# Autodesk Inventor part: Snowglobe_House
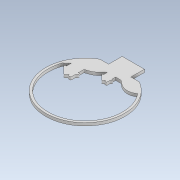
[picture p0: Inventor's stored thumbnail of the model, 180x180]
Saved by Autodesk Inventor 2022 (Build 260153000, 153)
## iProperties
Created: 2021-12
Part Number: Snowglobe_House
Material: Generic
Document SubType Name: Modeling
Designer: allis
Density: 1 g/cm^3
Appearance: Default
Author: allis
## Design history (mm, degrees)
sketch "Sketch1"
  geometry: L1 (18.282, -77.899)-(18.439, -77.803); L2 (18.439, -77.803)-(18.526, -77.758); L3 (18.526, -77.758)-(18.604, -77.703); L4 (18.604, -77.703)-(22.58, -74.861); L5 (22.58, -74.861)-(26.905, -74.228); L6 (26.905, -74.228)-(31.532, -75.726); L7 (31.532, -75.726)-(34.469, -76.677); L8 (34.469, -76.677)-(36.957, -78.398); L9 (36.957, -78.398)-(39.204, -80.475); L10 (39.204, -80.475)-(39.975, -81.188); L11 (39.975, -81.188)-(40.866, -81.529); L12 (40.866, -81.529)-(41.886, -81.542); L13 (41.886, -81.542)-(43.502, -81.564); L14 (43.502, -81.564)-(45.119, -81.548); L15 (45.119, -81.548)-(46.737, -81.548); L16 (46.737, -81.548)-(46.737, -80.096); L17 (46.737, -80.096)-(46.737, -78.696); L18 (46.737, -78.696)-(46.737, -77.291); L19 (46.737, -77.291)-(46.639, -77.297); L20 (46.639, -77.297)-(46.582, -77.296); L21 (46.582, -77.296)-(46.526, -77.303); L22 (46.526, -77.303)-(46.142, -77.355); L23 (46.142, -77.355)-(45.826, -77.267); L24 (45.826, -77.267)-(45.645, -76.887); L25 (45.645, -76.887)-(45.465, -76.51); L26 (45.465, -76.51)-(45.599, -76.205); L27 (45.599, -76.205)-(45.863, -75.929); L28 (45.863, -75.929)-(46.087, -75.695); L29 (46.087, -75.695)-(46.336, -75.48); L30 (46.336, -75.48)-(46.53, -75.223); L31 (46.53, -75.223)-(46.662, -75.047); L32 (46.662, -75.047)-(46.787, -74.816); L33 (46.787, -74.816)-(46.794, -74.606); L34 (46.794, -74.606)-(46.825, -73.774); L35 (46.825, -73.774)-(46.801, -72.941); L36 (46.801, -72.941)-(46.811, -72.109); L37 (46.811, -72.109)-(46.816, -71.673); L38 (46.816, -71.673)-(47.002, -71.488); L39 (47.002, -71.488)-(47.426, -71.475); L40 (47.426, -71.475)-(47.792, -71.464); L41 (47.792, -71.464)-(48.16, -71.458); L42 (48.16, -71.458)-(48.526, -71.468); L43 (48.526, -71.468)-(48.97, -71.48); L44 (48.97, -71.48)-(49.162, -71.679); L45 (49.162, -71.679)-(49.186, -72.116); L46 (49.186, -72.116)-(49.192, -72.223); L47 (49.192, -72.223)-(49.2, -72.33); L48 (49.2, -72.33)-(49.213, -72.513); L49 (49.213, -72.513)-(49.72, -72.016); L50 (49.72, -72.016)-(50.185, -71.574); L51 (50.185, -71.574)-(50.634, -71.117); L52 (50.634, -71.117)-(51.122, -70.622); L53 (51.122, -70.622)-(51.513, -70.607); L54 (51.513, -70.607)-(52.007, -71.097); L55 (52.007, -71.097)-(53.13, -72.209); L56 (53.13, -72.209)-(54.254, -73.32); L57 (54.254, -73.32)-(55.37, -74.439); L58 (55.37, -74.439)-(55.907, -74.978); L59 (55.907, -74.978)-(56.454, -75.512); L60 (56.454, -75.512)-(56.938, -76.097); L61 (56.938, -76.097)-(57.082, -76.271); L62 (57.082, -76.271)-(57.102, -76.624); L63 (57.102, -76.624)-(57.048, -76.865); L64 (57.048, -76.865)-(56.979, -77.174)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; 1 further point
  constraints: 2 other
extrude "Extrusion1" new body sketch "Sketch1" distance "d0" = 3.175; taper "d1" = 0 deg
feature "Move Body1"
body "Solid1"
other parameters: "d2" = 90 deg
